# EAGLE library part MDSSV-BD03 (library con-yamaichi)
YAMAICHI CONNECTOR
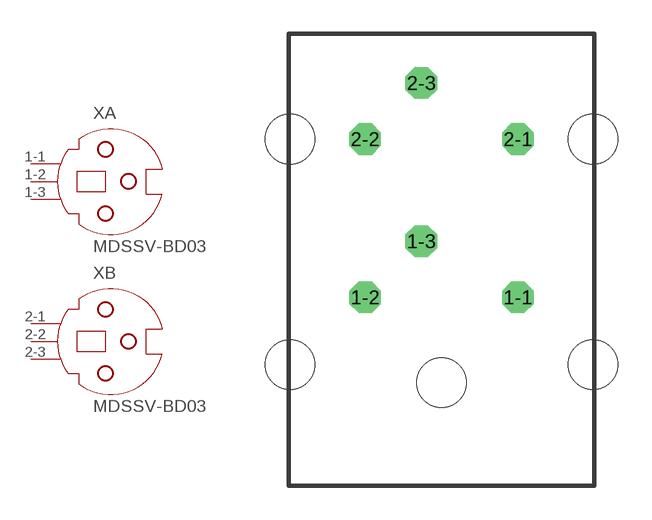
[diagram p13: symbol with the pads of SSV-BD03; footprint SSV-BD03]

Designator prefix X; gates A=SSV-BC03 B=SSV-BC03

## MDSSV-BD03 (OC_FARNELL: unknown; OC_NEWARK: unknown)  [SSV-BD03]
1-1  A:1  pas
1-2  A:2  pas
1-3  A:3  pas
2-1  B:1  pas
2-2  B:2  pas
2-3  B:3  pas

## Footprint SSV-BD03 (pad centres in mm)
Mini Din YAMAICHI CONNECTOR
drill 0.9 octagon: 1-1 3.4,8.5; 1-2 -3.4,8.5; 1-3 -0.9,11; 2-1 3.4,15.55; 2-2 -3.4,15.55; 2-3 -0.9,18.05
hole 2.2 at -6.75,5.5
hole 2.2 at 0,4.7
hole 2.2 at 6.75,5.5
hole 2.2 at -6.75,15.55
hole 2.2 at 6.75,15.55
